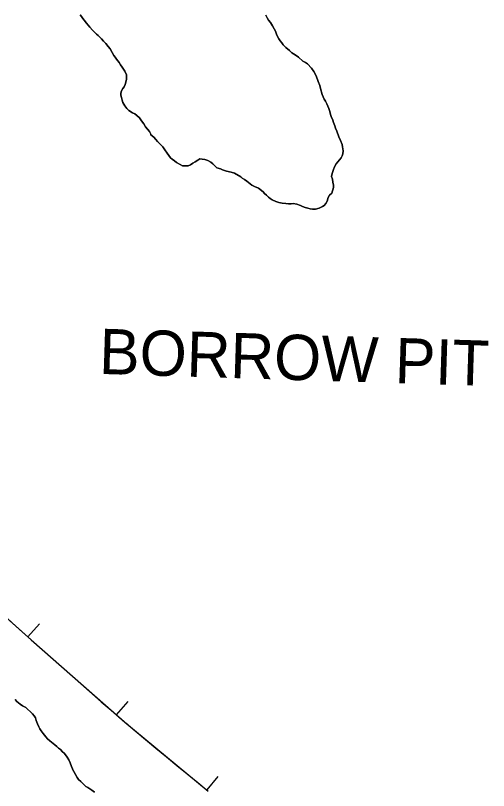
# Model space of a CAD drawing. Extents: x 3180038 to 3217926, y 922069 to 947485.
# Drawn here: x 3194174 to 3194843, y 942147 to 943243 of the extents above; entities that cross this region are included whole.
import ezdxf

# ---------------------------------------------------------------- set-up
doc = ezdxf.new("R2010")
doc.units = 0
for name, color, linetype in [('V-BORW-IDEN', 7, 'Continuous'), ('V-BORW-LINE', 7, 'Continuous'), ('V-SITE-VEGE', 7, 'Continuous'), ('V-TOPO-SHOR', 7, 'Continuous')]:
    doc.layers.add(name, color=color, linetype=linetype)

msp = doc.modelspace()

# ---------------------------------------------------------------- linework, layer by layer
at = {"layer": 'V-BORW-LINE'}
for p, q in [((3194162.9, 942389.6), (3194179.4, 942374.9)), ((3194179.4, 942374.9), (3194195.9, 942360.2)), ((3194191.4, 942364.2), (3194208, 942382.9)), ((3194195.9, 942360.2), (3194212.4, 942345.5)), ((3194212.4, 942345.5), (3194228.9, 942330.9)), ((3194228.9, 942330.9), (3194245.4, 942316.3)), ((3194245.4, 942316.3), (3194261.9, 942301.6)), ((3194261.9, 942301.6), (3194278.5, 942287.1)), ((3194278.5, 942287.1), (3194295.2, 942272.6)), ((3194295.2, 942272.6), (3194311.9, 942258.2)), ((3194316.6, 942254.3), (3194333.1, 942273.1)), ((3194343.2, 942231.5), (3194357.9, 942219.2)), ((3194357.9, 942219.2), (3194372.6, 942206.9)), ((3194372.6, 942206.9), (3194387.3, 942194.7)), ((3194387.3, 942194.7), (3194402.1, 942182.6)), ((3194402.1, 942182.6), (3194416.9, 942170.5)), ((3194416.9, 942170.5), (3194431.7, 942158.4)), ((3194444.8, 942147.9), (3194460.7, 942167.1)), ((3194431.7, 942158.4), (3194446.6, 942146.4))]:
    msp.add_line(p, q, dxfattribs=at)
for points in [[(3194063.9, 942477.5), (3194195.9, 942360.2)], [(3194195.9, 942360.2), (3194328.6, 942243.8)], [(3194328.6, 942243.8), (3194446.6, 942146.4)]]:
    msp.add_lwpolyline(points, dxfattribs=at)
msp.add_spline([(3194311.9, 942258.2), (3194328.6, 942243.8), (3194343.2, 942231.5)], degree=3, dxfattribs=at)
at = {"layer": 'V-SITE-VEGE'}
for points in [[(3194414.6, 943030.1), (3194410, 943030.2), (3194406.6, 943031.9), (3194401.8, 943035.1), (3194398.9, 943037.1), (3194395.5, 943039.4), (3194393, 943041.7), (3194388.4, 943048), (3194385.3, 943052.6), (3194382.5, 943056.9), (3194380, 943059.2), (3194374.6, 943064.7), (3194372.3, 943067.3), (3194369.5, 943070.5), (3194365.5, 943074.2), (3194365.5, 943074.8), (3194363.3, 943078.5), (3194360.4, 943082.2), (3194357.6, 943085.4), (3194355.6, 943089.4), (3194352.2, 943093.7), (3194349.1, 943098), (3194345.7, 943101.5), (3194342.6, 943103.5), (3194339.2, 943105.3), (3194334.4, 943108.4), (3194331.5, 943111.3), (3194328.7, 943115.1), (3194325.9, 943119.9), (3194324.8, 943123.1), (3194323.6, 943126.8), (3194322.8, 943130), (3194322.8, 943133.1), (3194323.7, 943136.2), (3194325.5, 943139.6), (3194327.8, 943141.9), (3194328.9, 943145), (3194329.8, 943148.5), (3194330.7, 943152.7), (3194330.7, 943159), (3194328.5, 943164.2), (3194324.8, 943169.6), (3194322.6, 943172.8), (3194320.3, 943176.3), (3194316.9, 943181.1), (3194314.9, 943183.7), (3194313.2, 943186.3), (3194310.4, 943190.3), (3194307.6, 943195.5), (3194304.8, 943198.9), (3194301.7, 943203), (3194298.3, 943206.4), (3194295.4, 943209.9), (3194293.2, 943212.2), (3194290.9, 943214.2), (3194288.6, 943216.2), (3194285.5, 943219.1), (3194282.7, 943222), (3194279, 943226.3), (3194276.7, 943228.9), (3194274.2, 943231.7), (3194270.8, 943236.1), (3194269.1, 943238.6), (3194267.4, 943241.2), (3194265.4, 943243.5)], [(3194528.2, 943243.2), (3194529.9, 943239.2), (3194531.9, 943236), (3194534.7, 943232.6), (3194537.2, 943228.3), (3194539.8, 943224), (3194541.5, 943220.5), (3194543.2, 943216.2), (3194544.3, 943213.1), (3194546.2, 943209.9), (3194548.2, 943206.8), (3194550.5, 943203.9), (3194552.7, 943201.3), (3194556.4, 943197.6), (3194561.5, 943193)], [(3194561.5, 943193), (3194564.9, 943190.1), (3194569.5, 943187.2), (3194574, 943184), (3194580.3, 943178.2), (3194584, 943176.2), (3194587.1, 943174.2), (3194592.8, 943168.4), (3194595.9, 943163.3), (3194599, 943157.5), (3194602.1, 943149.2), (3194604.3, 943143.5), (3194605.4, 943139.5), (3194607.6, 943130.9), (3194610.4, 943124.3), (3194612.4, 943121.4), (3194614.1, 943118), (3194615.8, 943114.3), (3194616.9, 943111.1), (3194618.3, 943107.1), (3194619.4, 943102.8), (3194620.5, 943099.9), (3194622.8, 943094.5), (3194623.9, 943091.6), (3194625.8, 943086.5), (3194626.7, 943083.3), (3194628.4, 943079), (3194631.4, 943071.3), (3194633.7, 943066.1), (3194635.9, 943060.4), (3194636.5, 943057), (3194637.3, 943051.5), (3194636.7, 943047.2), (3194635.8, 943044.1), (3194634.4, 943041.3), (3194632.1, 943038.7), (3194629.7, 943035.9), (3194627.4, 943033), (3194625.1, 943028.8), (3194623.7, 943025.1), (3194621.6, 943019.4), (3194621, 943015.1), (3194622.4, 943011.4), (3194622.9, 943007.1), (3194623.5, 943002.8), (3194623.5, 942999.4), (3194621.1, 942991.4), (3194618.2, 942988.5), (3194616.2, 942985.4), (3194614.5, 942980.3), (3194612.7, 942976.9), (3194610.7, 942974.3), (3194608.1, 942972.6), (3194603.5, 942970.1), (3194598.1, 942969), (3194594.1, 942968.7), (3194590.7, 942969.3), (3194587.2, 942970.2), (3194583.8, 942971.4), (3194579.8, 942972.8), (3194577, 942974), (3194571.6, 942975.8), (3194566.7, 942976.7), (3194563.6, 942976.4), (3194559.9, 942976.4), (3194556.4, 942976.7), (3194551, 942977.4), (3194546.5, 942978.2), (3194542.2, 942979.7), (3194536.8, 942982), (3194534.2, 942984.1), (3194531.9, 942986.1), (3194529.1, 942988.7), (3194526.3, 942991), (3194524.3, 942993.3), (3194517.5, 942998.5), (3194511.8, 943000.8), (3194508.1, 943002.8), (3194501, 943008.3), (3194497.6, 943010.9), (3194494.7, 943012.6), (3194492.5, 943014.7), (3194483.6, 943019.6), (3194478.8, 943021.3), (3194472.5, 943022.8), (3194466.5, 943024.6), (3194463.7, 943025.7), (3194458.8, 943027.5), (3194456, 943030.4), (3194452.9, 943033), (3194450.1, 943035.3), (3194446.1, 943037.9), (3194441.8, 943039), (3194437.8, 943039.4), (3194434.4, 943040), (3194431.8, 943038.3), (3194427.8, 943036), (3194424.9, 943033.8), (3194421.2, 943031.8), (3194418.3, 943030.4), (3194414.6, 943030.1)], [(3194173.3, 942275.9), (3194176, 942273), (3194180.3, 942269.4), (3194183.6, 942266.8), (3194188.6, 942264.3), (3194188.8, 942264.1), (3194190.9, 942262.3), (3194195.2, 942258.5), (3194197.9, 942255.6), (3194200.3, 942252.8), (3194202.1, 942249.9), (3194203.3, 942246.1), (3194204.9, 942241.3), (3194206.7, 942237.3), (3194208.3, 942234.3), (3194210, 942231.6), (3194213, 942227.6), (3194216.6, 942223.1), (3194219.4, 942220), (3194222.3, 942217.5), (3194227.2, 942213.5), (3194229.7, 942211.6), (3194232.2, 942209.2), (3194234.7, 942207.2), (3194237.4, 942205.2), (3194240.6, 942202), (3194242.7, 942199.8), (3194244.8, 942197.7), (3194247.1, 942194.4), (3194249.2, 942190.5), (3194251, 942186.2), (3194253.1, 942181), (3194254.5, 942177.9), (3194254.7, 942177.2), (3194256.3, 942174), (3194258.6, 942169.7), (3194260.9, 942165.7), (3194263.2, 942162.8), (3194266.2, 942159.8), (3194270.1, 942156), (3194273.6, 942152.9), (3194276.3, 942151.3), (3194279, 942149.6), (3194281.8, 942147.5), (3194285.6, 942144.6)]]:
    msp.add_lwpolyline(points, dxfattribs=at)
at = {"layer": 'V-TOPO-SHOR'}
for points in [[(3194265.4, 943243.5), (3194267.4, 943241.2), (3194269.1, 943238.6), (3194270.8, 943236.1), (3194274.2, 943231.7), (3194276.7, 943228.9)], [(3194579.8, 942972.8), (3194583.8, 942971.4), (3194587.2, 942970.2), (3194590.7, 942969.3), (3194594.1, 942968.7), (3194598.1, 942969), (3194603.5, 942970.1), (3194608.1, 942972.6), (3194610.7, 942974.3), (3194612.7, 942976.9), (3194614.5, 942980.3), (3194616.2, 942985.4), (3194618.2, 942988.5), (3194621.1, 942991.4), (3194623.5, 942999.4), (3194623.5, 943002.8), (3194622.9, 943007.1), (3194622.4, 943011.4), (3194621, 943015.1), (3194621.6, 943019.4), (3194623.7, 943025.1), (3194625.1, 943028.8), (3194627.4, 943033), (3194629.7, 943035.9), (3194632.1, 943038.7), (3194634.4, 943041.3), (3194635.8, 943044.1), (3194636.7, 943047.3), (3194637.3, 943051.5), (3194636.5, 943057), (3194635.9, 943060.4), (3194633.7, 943066.1), (3194631.4, 943071.3), (3194628.4, 943079), (3194626.7, 943083.3), (3194625.8, 943086.5), (3194623.9, 943091.6), (3194622.8, 943094.5), (3194620.5, 943099.9), (3194619.4, 943102.8), (3194618.3, 943107.1), (3194616.9, 943111.1), (3194615.8, 943114.3), (3194614.1, 943118), (3194612.4, 943121.4), (3194610.4, 943124.3), (3194607.6, 943130.9), (3194605.4, 943139.5), (3194604.3, 943143.5), (3194602.1, 943149.2), (3194599, 943157.5), (3194595.9, 943163.3), (3194592.8, 943168.4), (3194587.1, 943174.2), (3194584, 943176.2), (3194580.3, 943178.2), (3194574, 943184), (3194569.5, 943187.2), (3194564.9, 943190.1), (3194561.5, 943193), (3194556.4, 943197.6), (3194552.7, 943201.3), (3194550.5, 943203.9), (3194548.2, 943206.8), (3194546.2, 943209.9), (3194544.3, 943213.1), (3194543.2, 943216.2), (3194541.5, 943220.5), (3194539.8, 943224), (3194537.2, 943228.3), (3194534.7, 943232.6), (3194531.9, 943236), (3194529.9, 943239.2), (3194528.2, 943243.2)], [(3194276.7, 943228.9), (3194279, 943226.3), (3194282.7, 943222), (3194285.5, 943219.1), (3194288.6, 943216.2), (3194290.9, 943214.2), (3194293.2, 943212.2), (3194295.4, 943209.9), (3194298.3, 943206.4), (3194301.7, 943203), (3194304.8, 943198.9), (3194307.6, 943195.5), (3194310.4, 943190.3), (3194313.2, 943186.3), (3194314.9, 943183.7), (3194316.9, 943181.1), (3194320.3, 943176.3), (3194322.6, 943172.8), (3194324.8, 943169.6), (3194328.5, 943164.2), (3194330.7, 943159), (3194330.7, 943152.7), (3194329.8, 943148.5), (3194328.9, 943145), (3194327.8, 943141.9), (3194325.5, 943139.6), (3194323.7, 943136.2), (3194322.8, 943133.1), (3194322.8, 943130), (3194323.6, 943126.8), (3194324.8, 943123.1), (3194325.9, 943119.9), (3194328.7, 943115.1), (3194331.5, 943111.3), (3194334.4, 943108.4), (3194339.2, 943105.3), (3194342.6, 943103.5), (3194345.7, 943101.5), (3194349.1, 943098), (3194352.2, 943093.7), (3194355.6, 943089.4), (3194357.6, 943085.4), (3194360.4, 943082.2), (3194363.3, 943078.5), (3194365.5, 943074.8), (3194365.5, 943074.2), (3194369.5, 943070.5), (3194372.3, 943067.3), (3194374.6, 943064.7), (3194380, 943059.2), (3194382.5, 943056.9), (3194385.3, 943052.6), (3194388.4, 943048), (3194393, 943041.7), (3194395.5, 943039.4), (3194398.9, 943037.1), (3194401.8, 943035.1), (3194406.6, 943031.9), (3194410, 943030.2), (3194414.6, 943030.1), (3194418.3, 943030.4), (3194421.2, 943031.8), (3194424.9, 943033.8), (3194427.8, 943036), (3194431.8, 943038.3), (3194434.4, 943040), (3194437.8, 943039.4), (3194441.8, 943039), (3194446.1, 943037.9), (3194450.1, 943035.3), (3194452.9, 943033), (3194456, 943030.4), (3194458.8, 943027.5), (3194463.7, 943025.7), (3194466.5, 943024.6), (3194472.5, 943022.8), (3194478.8, 943021.3), (3194483.6, 943019.6), (3194492.5, 943014.7), (3194494.7, 943012.6), (3194497.6, 943010.9), (3194501, 943008.3), (3194508.1, 943002.8), (3194511.8, 943000.8), (3194517.5, 942998.5), (3194524.3, 942993.3), (3194526.3, 942991), (3194529.1, 942988.7), (3194531.9, 942986.1), (3194534.2, 942984.1), (3194536.8, 942982), (3194542.2, 942979.7), (3194546.5, 942978.2), (3194551, 942977.4), (3194556.4, 942976.7), (3194559.9, 942976.4), (3194563.6, 942976.4), (3194566.7, 942976.7), (3194571.6, 942975.8), (3194577, 942974), (3194579.8, 942972.8)], [(3194285.6, 942144.6), (3194281.8, 942147.5), (3194279, 942149.6), (3194276.3, 942151.3), (3194273.6, 942152.9), (3194270.1, 942156), (3194266.2, 942159.8), (3194263.2, 942162.8), (3194260.9, 942165.7), (3194258.6, 942169.7), (3194256.3, 942174), (3194254.7, 942177.2), (3194254.5, 942177.9), (3194253.1, 942181), (3194251, 942186.2), (3194249.2, 942190.5), (3194247.1, 942194.4), (3194244.8, 942197.7), (3194242.7, 942199.8), (3194240.6, 942202), (3194237.4, 942205.2), (3194234.7, 942207.2), (3194232.2, 942209.2), (3194229.7, 942211.6), (3194227.2, 942213.5), (3194222.3, 942217.5), (3194219.4, 942220), (3194216.6, 942223.1), (3194213, 942227.6), (3194210, 942231.6), (3194208.3, 942234.3), (3194206.7, 942237.3), (3194204.9, 942241.3), (3194203.3, 942246.1), (3194202.1, 942249.9), (3194200.3, 942252.8), (3194197.9, 942255.6), (3194195.2, 942258.5), (3194190.9, 942262.3), (3194188.8, 942264.1), (3194188.6, 942264.3), (3194183.6, 942266.8), (3194180.3, 942269.4), (3194176, 942273), (3194173.3, 942275.9)]]:
    msp.add_lwpolyline(points, dxfattribs=at)

# ---------------------------------------------------------------- texts
at = {"layer": 'V-BORW-IDEN'}
msp.add_text('BORROW PIT', height=64, rotation=358.2133, dxfattribs=at).set_placement((3194291.6, 942736.1))

doc.saveas('drawing.dxf')
